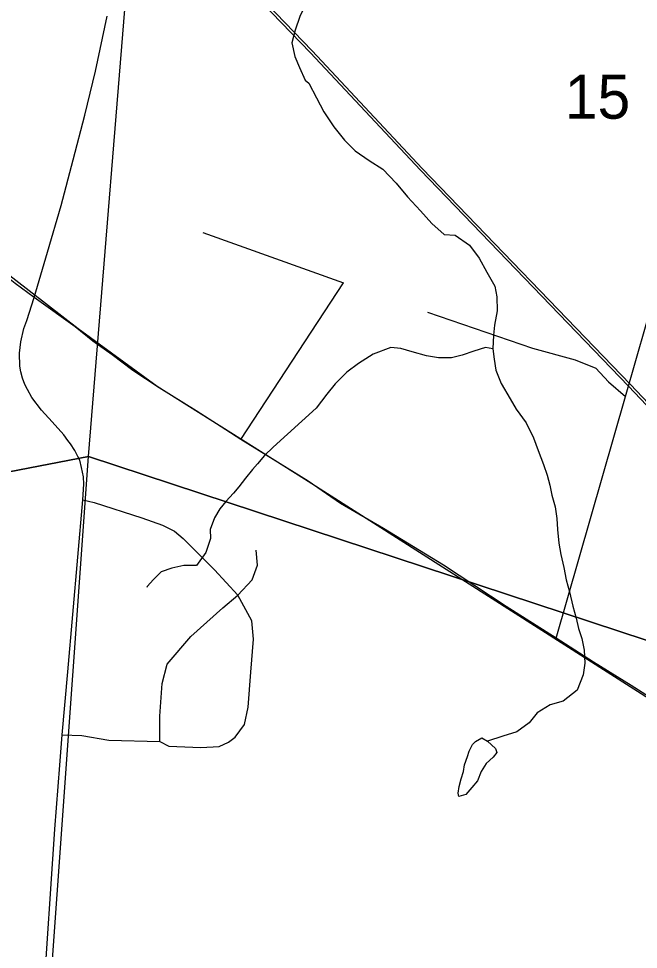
# Model space of a CAD drawing. Extents: x 0 to 34, y 0 to 22.
# Drawn here: x 2.317 to 2.906, y 16.249 to 17.132 of the extents above; entities that cross this region are included whole.
import ezdxf

# ---------------------------------------------------------------- set-up
doc = ezdxf.new("R2010")
doc.units = 0
for name, color, linetype in [('Default', 7, 'Continuous'), ('GM_X_City_Street', 7, 'Continuous'), ('GM_X_County_Road', 7, 'Continuous'), ('GM_X_Minor_River', 7, 'Continuous'), ('GM_X_Rail_Line', 7, 'Continuous'), ('GM_X_Section', 7, 'Continuous'), ('GM_X_Section_Text', 7, 'Continuous'), ('GM_X_State_Route', 7, 'Continuous')]:
    doc.layers.add(name, color=color, linetype=linetype)

msp = doc.modelspace()

# ---------------------------------------------------------------- linework, layer by layer
at = {"layer": 'Default'}
for points in [[(2.1, 17.66661), (2.1, 16.66194), (2.38346, 16.71678), (2.46777, 17.75239)], [(2.1, 16.66194), (2.1, 15.64957), (2.30941, 15.68168), (2.38346, 16.71678)]]:
    msp.add_lwpolyline(points, close=True, dxfattribs=at)
at = {"layer": 'GM_X_City_Street'}
for p in [(2.49228, 16.9295), (2.52809, 16.73279)]:
    msp.add_line(p, (2.62569, 16.88153), dxfattribs=at)
for points in [[(2.82756, 16.54429), (2.89344, 16.77389), (2.92304, 16.87615), (2.99008, 17.11211), (3.006, 17.16133), (3.02619, 17.54394), (3.02633, 17.54659), (3.02667, 17.55287), (3.0555, 18.06084), (3.07082, 18.27886), (3.0961, 18.5247), (3.1069, 18.68439), (3.11632, 18.80103)], [(2.70535, 16.8537), (2.80513, 16.81951), (2.84565, 16.80849), (2.86522, 16.80077), (2.87735, 16.78782), (2.89344, 16.77389)], [(2.37824, 16.67559), (2.38907, 16.67313), (2.43434, 16.65853), (2.45385, 16.65148), (2.46517, 16.64606), (2.47347, 16.63901), (2.50319, 16.60936), (2.52531, 16.58517)], [(2.52531, 16.58517), (2.53884, 16.59985), (2.54403, 16.61369), (2.54262, 16.62784)], [(2.35864, 16.45259), (2.37728, 16.4521), (2.403, 16.44744), (2.45121, 16.44632), (2.45973, 16.44198), (2.49027, 16.4407), (2.50763, 16.4415), (2.51663, 16.44568), (2.5229, 16.4505), (2.53158, 16.46239), (2.53511, 16.47895), (2.53785, 16.51222), (2.5401, 16.5434), (2.53881, 16.56091), (2.52531, 16.58517)], [(2.45121, 16.44632), (2.45126, 16.45647), (2.45115, 16.47037), (2.45367, 16.50116), (2.45816, 16.51955), (2.48072, 16.54596), (2.51118, 16.57312), (2.52531, 16.58517)]]:
    msp.add_lwpolyline(points, dxfattribs=at)
at = {"layer": 'GM_X_County_Road'}
for points in [[(2.36406, 16.73186), (2.36004, 16.73734), (2.34905, 16.74964), (2.339, 16.76084), (2.32961, 16.77268), (2.32551, 16.78039), (2.32305, 16.78514), (2.32076, 16.79105), (2.31928, 16.79728), (2.31827, 16.80268), (2.31813, 16.81483), (2.31928, 16.82566), (2.32223, 16.83845), (2.32505, 16.84603), (2.33207, 16.86781)], [(2.34052, 16.19782), (2.35167, 16.36298), (2.35639, 16.42382), (2.35864, 16.45259), (2.36398, 16.51239), (2.37824, 16.67559), (2.37898, 16.69043), (2.37874, 16.6974), (2.37701, 16.7065), (2.37529, 16.71331), (2.37349, 16.71683), (2.3707, 16.72241), (2.36635, 16.72872), (2.36406, 16.73186)]]:
    msp.add_lwpolyline(points, dxfattribs=at)
at = {"layer": 'GM_X_Minor_River'}
for points in [[(2.4582, 17.25795), (2.46604, 17.25098), (2.47958, 17.24567), (2.49321, 17.24378), (2.50491, 17.2408), (2.52373, 17.2342), (2.53568, 17.22627), (2.54943, 17.21486), (2.56013, 17.20315), (2.57344, 17.18947), (2.58516, 17.17355), (2.59089, 17.16084), (2.59053, 17.14753), (2.58409, 17.13438), (2.57993, 17.12155), (2.57656, 17.10946), (2.57962, 17.09644), (2.5839, 17.08605), (2.58928, 17.07411)], [(2.58928, 17.07411), (2.59294, 17.07103), (2.60019, 17.05716), (2.60708, 17.04405), (2.6166, 17.02974), (2.62653, 17.01694), (2.63691, 17.0068), (2.64998, 16.99772), (2.66307, 16.9894), (2.67565, 16.97615), (2.68635, 16.96333), (2.69893, 16.95009), (2.70965, 16.93803), (2.72116, 16.92747), (2.73178, 16.92682), (2.74522, 16.91735), (2.7544, 16.90495), (2.76167, 16.89184), (2.76931, 16.87834), (2.77134, 16.8684), (2.77177, 16.85508), (2.76915, 16.84146), (2.76815, 16.83199), (2.76745, 16.81907), (2.76873, 16.80916), (2.77037, 16.79885), (2.77537, 16.78618), (2.78412, 16.77151), (2.78958, 16.76186), (2.79912, 16.74869), (2.80599, 16.73445), (2.81063, 16.72254), (2.81561, 16.70911), (2.81916, 16.69913), (2.82158, 16.68957), (2.82362, 16.68001), (2.82676, 16.66891), (2.82839, 16.65784), (2.82889, 16.64756), (2.83009, 16.6346), (2.8321, 16.6239), (2.83483, 16.61129), (2.8372, 16.59982), (2.84033, 16.58834), (2.84341, 16.57457), (2.84655, 16.56346), (2.84896, 16.55352), (2.85214, 16.54393), (2.85415, 16.53285), (2.85498, 16.52066), (2.85319, 16.50968), (2.84751, 16.495), (2.83434, 16.48469), (2.82209, 16.4812), (2.80975, 16.47353), (2.80191, 16.46384), (2.79031, 16.45539), (2.77691, 16.45117)], [(2.76745, 16.81907), (2.76065, 16.82039), (2.74955, 16.81687), (2.73843, 16.81297), (2.72812, 16.81057), (2.71596, 16.8105), (2.70461, 16.81231), (2.69103, 16.81608), (2.68009, 16.8194), (2.67062, 16.8204), (2.65375, 16.81399), (2.63986, 16.80522), (2.62901, 16.79675), (2.61772, 16.78563), (2.60988, 16.77595), (2.59967, 16.76252)], [(2.55886, 16.72554), (2.59967, 16.76252)], [(2.55886, 16.72554), (2.55069, 16.71777), (2.54404, 16.70995), (2.53934, 16.70437), (2.53268, 16.69617), (2.5264, 16.68797), (2.52132, 16.68202), (2.5139, 16.67422), (2.50841, 16.66713), (2.50326, 16.65852), (2.49919, 16.6476), (2.49935, 16.63885), (2.49484, 16.62566), (2.48618, 16.61333), (2.47402, 16.61326), (2.46257, 16.61089), (2.4526, 16.60735), (2.4452, 16.59993), (2.43934, 16.59324), (2.43894, 16.59249)], [(2.76236, 16.4466), (2.77016, 16.43956), (2.77121, 16.43573), (2.76767, 16.43126), (2.76107, 16.42534), (2.75633, 16.41786), (2.75306, 16.40882), (2.74759, 16.40249), (2.74173, 16.3958), (2.73523, 16.39406), (2.73454, 16.39712), (2.73546, 16.40356), (2.73754, 16.41073), (2.73961, 16.4179), (2.74053, 16.42396)], [(2.74053, 16.42396), (2.74338, 16.43188), (2.74503, 16.43716), (2.74823, 16.44354), (2.75095, 16.44613), (2.75712, 16.44978), (2.76236, 16.4466)], [(2.77691, 16.45117), (2.76236, 16.4466)]]:
    msp.add_lwpolyline(points, dxfattribs=at)
at = {"layer": 'GM_X_Rail_Line'}
for points in [[(4.20391, 15.41642), (3.74391, 15.89669), (3.34284, 16.31693), (3.15304, 16.51618), (2.89818, 16.78515), (2.70052, 16.99019), (2.596, 17.10186), (2.43236, 17.27175), (2.1, 17.62138)], [(4.20107, 15.4158), (3.74211, 15.89497), (3.34104, 16.31522), (3.15124, 16.51447), (2.89639, 16.78343), (2.69872, 16.98848), (2.5942, 17.10014), (2.43056, 17.27003), (2.1, 17.61777)], [(3.34444, 15.37384), (3.24995, 15.83275), (3.23923, 15.90963), (3.23757, 15.97369), (3.24246, 16.11331), (3.23802, 16.19204), (3.20138, 16.28414), (3.14367, 16.3394), (3.03229, 16.41226), (2.58864, 16.69515), (2.44885, 16.78313), (2.37378, 16.83814), (2.1, 17.0501)]]:
    msp.add_lwpolyline(points, dxfattribs=at)
at = {"layer": 'GM_X_Section'}
for points in [[(2.46777, 17.75239), (3.55718, 17.36386), (3.47043, 16.3589), (2.38346, 16.71678)], [(2.38346, 16.71678), (3.47043, 16.3589), (3.38505, 15.36453), (2.30941, 15.68168)]]:
    msp.add_lwpolyline(points, close=True, dxfattribs=at)
at = {"layer": 'GM_X_State_Route'}
for points in [[(2.33207, 16.86781), (2.34462, 16.91074), (2.35753, 16.95497), (2.36885, 16.99829), (2.38016, 17.04081), (2.39011, 17.08253), (2.40125, 17.13476)], [(2.33207, 16.86781), (2.31385, 16.88089), (2.30769, 16.88602)], [(2.82756, 16.54429), (2.78011, 16.5743), (2.72051, 16.61361), (2.66373, 16.64835), (2.62294, 16.67232), (2.59206, 16.69327), (2.55899, 16.71394), (2.52809, 16.73279), (2.50965, 16.74509), (2.48566, 16.76025), (2.45066, 16.78203), (2.42558, 16.79857), (2.406, 16.81345), (2.38754, 16.82641), (2.37077, 16.8399), (2.33207, 16.86781)], [(2.98927, 16.44378), (2.96758, 16.45719), (2.93637, 16.47583), (2.89871, 16.49932), (2.86314, 16.52142), (2.82756, 16.54429)]]:
    msp.add_lwpolyline(points, dxfattribs=at)

# ---------------------------------------------------------------- texts
at = {"layer": 'GM_X_Section_Text'}
msp.add_text('15', height=0.041856, rotation=0.00001, dxfattribs=at).set_placement((2.83579, 17.03741))

doc.saveas('drawing.dxf')
